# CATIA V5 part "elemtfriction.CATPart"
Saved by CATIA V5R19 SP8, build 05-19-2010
Part number: elemtfriction
Bounding box of the stored display mesh (mm): x -23.133 to 0, y -58 to 58, z -57.82 to 57.82
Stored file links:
  U:\Rendu_cfao_elguidj\elemtfriction.CATPart
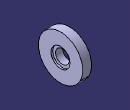
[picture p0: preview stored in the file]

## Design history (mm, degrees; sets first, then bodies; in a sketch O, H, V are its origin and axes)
Body1 (main body)
  DatumCurve1
  DatumSurface1
  DatumCurve2
  Sketch1 on xy-plane, origin (0, 0, 0), H (1, 0, 0), V (0, 1, 0)
    line L1 (0, 58) -> (0, 25)
    line L2 (0, 25) -> (-4.8, 25)
    line L3 (-4.8, 25) -> (-4.8, 18)
    line L4 (-4.8, 18) -> (-23.1329, 18)
    line L5 (-23.1329, 18) -> (-23.1329, 58)
    line L6 (-23.1329, 58) -> (0, 58)
    reference projected line E1 (-4.8, -24.9506) -> (-4.8, 24.9506) from edge of DatumCurve1
    reference intersected line E2 through (-23.1329, 0) direction (0, -1) from face of DatumSurface1
    distance L2 H = 25
    length L3 = 7
    length L5 = 40
    vertical: L1 V, L3 V, L5 V
    horizontal: L2 H, L4 H, L6 H
    coincidence: L1 V, L3 E1, L5 E2
  Shaft1: profile Sketch1, axis edge of DatumCurve2, angle 360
